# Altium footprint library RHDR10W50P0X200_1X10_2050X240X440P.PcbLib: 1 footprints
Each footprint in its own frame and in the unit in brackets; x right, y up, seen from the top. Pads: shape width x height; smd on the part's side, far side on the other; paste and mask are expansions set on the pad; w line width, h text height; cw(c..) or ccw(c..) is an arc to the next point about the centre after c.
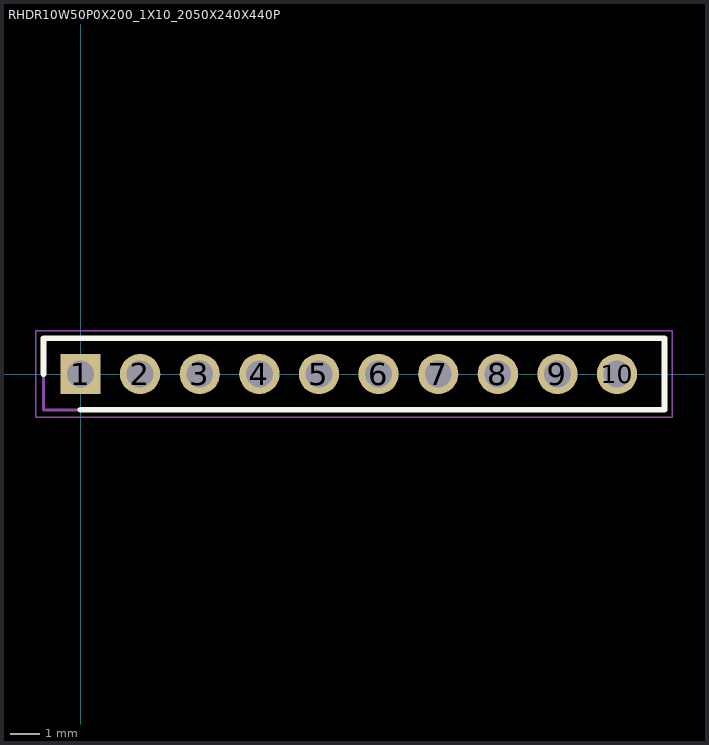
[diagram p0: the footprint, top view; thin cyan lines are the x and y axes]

## RHDR10W50P0X200_1X10_2050X240X440P [mm]
pads (10):
  rect 1.35x1.35 / inner round 1.35 / far side rect 1.35x1.35 hole 0.9: 1(0,0)
  round 1.35 hole 0.9: 2(2,0) 3(4,0) 4(6,0) 5(8,0) 6(10,0) 7(12,0) 8(14,0) 9(16,0) 10(18,0)
Top Overlay:
  lines w0.2: -1.25,0 -1.25,1.2 19.6,1.2 19.6,-1.2 0,-1.2
Mechanical 15:
  lines w0.1: -1.25,-1.2 -1.25,1.2 19.6,1.2 19.6,-1.2 -1.25,-1.2
Mechanical 20:
  lines w0.05: -1.5,-1.45 -1.5,1.45 19.85,1.45 19.85,-1.45 -1.5,-1.45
